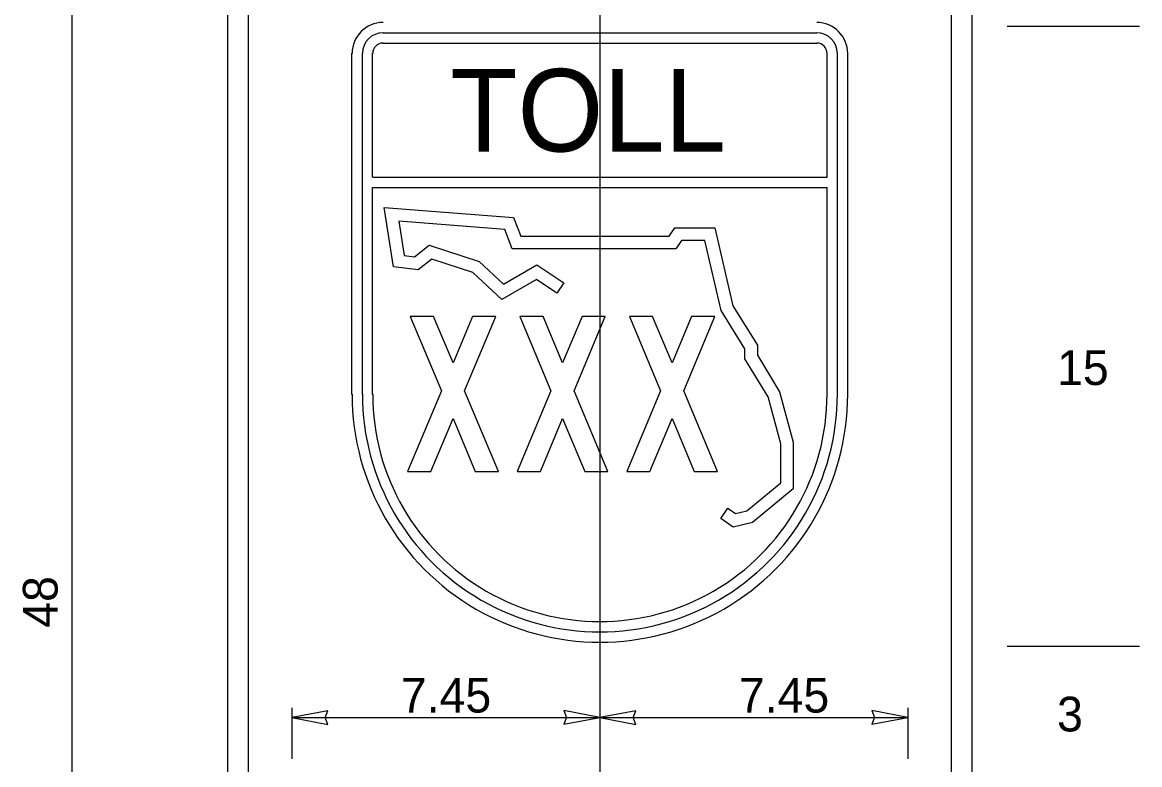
# Model space of a CAD drawing. Extents: x 56108 to 56734, y 11696 to 12110.
# Drawn here: x 56513 to 56603.2, y 11815.3 to 11875.2 of the extents above; entities that cross this region are included whole.
import ezdxf

# ---------------------------------------------------------------- set-up
doc = ezdxf.new("R2010")
doc.units = 0
for name, color, linetype in [('CL_dp', 7, 'Continuous'), ('GSDims', 7, 'Continuous'), ('SignDetail', 7, 'Continuous'), ('SignPanel', 7, 'Continuous')]:
    doc.layers.add(name, color=color, linetype=linetype)

msp = doc.modelspace()

# ---------------------------------------------------------------- linework, layer by layer
at = {"layer": 'CL_dp'}
msp.add_line((56559.633, 11917.974), (56559.633, 11745.618), dxfattribs=at)
at = {"layer": 'GSDims'}
for p, q in [((56517.038, 11913.158), (56517.038, 11753.158)), ((56603.176, 11874.825), (56592.496, 11874.825)), ((56547.759, 11858.728), (56547.759, 11858.728)), ((56603.176, 11824.825), (56592.496, 11824.825)), ((56534.799, 11819.883), (56534.799, 11815.752)), ((56537.699, 11819.631), (56534.799, 11819.091)), ((56537.479, 11819.091), (56537.699, 11819.631)), ((56559.633, 11819.091), (56556.733, 11819.651)), ((56556.733, 11819.651), (56556.953, 11819.091)), ((56562.533, 11819.631), (56559.633, 11819.091)), ((56562.313, 11819.091), (56562.533, 11819.631)), ((56584.466, 11819.091), (56581.566, 11819.651)), ((56581.566, 11819.651), (56581.786, 11819.091)), ((56584.466, 11819.883), (56584.466, 11815.752)), ((56534.799, 11819.091), (56559.633, 11819.091)), ((56534.799, 11819.091), (56537.699, 11818.531)), ((56537.699, 11818.531), (56537.479, 11819.091)), ((56556.953, 11819.091), (56556.733, 11818.551)), ((56556.733, 11818.551), (56559.633, 11819.091)), ((56559.633, 11819.091), (56584.466, 11819.091)), ((56559.633, 11819.091), (56562.533, 11818.531)), ((56562.533, 11818.531), (56562.313, 11819.091)), ((56581.786, 11819.091), (56581.566, 11818.551)), ((56581.566, 11818.551), (56584.466, 11819.091))]:
    msp.add_line(p, q, dxfattribs=at)
at = {"layer": 'SignDetail'}
for p, q in [((56542.135, 11874.323), (56577.137, 11874.323)), ((56539.636, 11845.149), (56539.636, 11872.663)), ((56540.475, 11845.149), (56540.475, 11872.663)), ((56541.295, 11862.665), (56541.295, 11872.663)), ((56542.135, 11873.483), (56577.137, 11873.483)), ((56577.957, 11862.665), (56577.957, 11872.663)), ((56578.796, 11845.149), (56578.796, 11872.663)), ((56579.636, 11845.149), (56579.636, 11872.663)), ((56541.295, 11862.665), (56577.957, 11862.665)), ((56541.295, 11845.149), (56541.295, 11861.825)), ((56541.295, 11861.825), (56577.957, 11861.825)), ((56577.957, 11845.149), (56577.957, 11861.825))]:
    msp.add_line(p, q, dxfattribs=at)
for centre, major_axis, start_param, end_param in [((56542.145, 11872.653), (0, 2.5), 0, 1.570796), ((56577.127, 11872.653), (0, 2.5), 4.712389, 6.283185), ((56542.145, 11872.653), (0, 1.666), 0, 1.570796), ((56577.127, 11872.653), (0, 1.666), 4.712389, 6.283185), ((56542.145, 11872.653), (0, 0.833), 0, 1.570796), ((56577.127, 11872.653), (0, 0.833), 4.712389, 6.283185), ((56559.636, 11845.159), (0, -19.996), 4.712389, 7.853982), ((56559.636, 11845.159), (0, -19.163), 4.712389, 7.853982), ((56559.636, 11845.159), (0, -18.33), 4.712389, 7.853982)]:
    msp.add_ellipse(centre, major_axis=major_axis, ratio=0.9997, start_param=start_param, end_param=end_param, dxfattribs=at)
at = {"layer": 'SignPanel'}
for p, q in [((56542.981, 11855.442), (56542.238, 11860.215)), ((56542.238, 11860.215), (56552.673, 11859.41)), ((56551.964, 11858.456), (56543.428, 11859.114)), ((56543.428, 11859.114), (56543.858, 11856.348)), ((56552.673, 11859.41), (56553.256, 11857.91)), ((56552.568, 11856.903), (56551.964, 11858.456)), ((56565.225, 11857.91), (56565.676, 11858.576)), ((56565.676, 11858.576), (56568.896, 11858.576)), ((56568.896, 11858.576), (56570.354, 11852.303)), ((56553.256, 11857.91), (56565.225, 11857.91)), ((56566.21, 11857.57), (56565.759, 11856.903)), ((56568.097, 11857.57), (56566.21, 11857.57)), ((56569.412, 11851.913), (56568.097, 11857.57)), ((56544.686, 11856.246), (56545.871, 11857.179)), ((56545.871, 11857.179), (56549.897, 11855.869)), ((56565.759, 11856.903), (56552.568, 11856.903)), ((56543.858, 11856.348), (56544.686, 11856.246)), ((56546.071, 11856.055), (56544.978, 11855.195)), ((56549.376, 11854.98), (56546.071, 11856.055)), ((56549.897, 11855.869), (56551.873, 11854.038)), ((56551.873, 11854.038), (56554.552, 11855.612)), ((56554.552, 11855.612), (56556.732, 11854.138)), ((56544.978, 11855.195), (56542.981, 11855.442)), ((56551.737, 11852.792), (56549.376, 11854.98)), ((56554.514, 11854.423), (56551.737, 11852.792)), ((56556.168, 11853.305), (56554.514, 11854.423)), ((56556.732, 11854.138), (56556.168, 11853.305)), ((56571.332, 11848.827), (56569.412, 11851.913)), ((56570.354, 11852.303), (56572.339, 11849.114)), ((56571.332, 11848.028), (56571.332, 11848.827)), ((56572.339, 11849.114), (56572.339, 11848.309)), ((56572.339, 11848.309), (56574.134, 11845.353)), ((56573.201, 11844.951), (56571.332, 11848.028)), ((56574.233, 11841.173), (56573.201, 11844.951)), ((56574.134, 11845.353), (56575.239, 11841.309)), ((56574.233, 11838.006), (56574.233, 11841.173)), ((56575.239, 11841.309), (56575.239, 11837.529)), ((56571.485, 11835.753), (56574.233, 11838.006)), ((56575.239, 11837.529), (56571.944, 11834.828)), ((56569.386, 11835.142), (56569.96, 11835.968)), ((56569.96, 11835.968), (56570.582, 11835.537)), ((56570.582, 11835.537), (56571.485, 11835.753)), ((56570.378, 11834.453), (56569.386, 11835.142)), ((56571.944, 11834.828), (56570.378, 11834.453))]:
    msp.add_line(p, q, dxfattribs=at)
for points in [[(56529.633, 11758.158), (56529.633, 11908.158)], [(56531.299, 11758.158), (56531.299, 11908.158)], [(56587.966, 11908.158), (56587.966, 11758.158)], [(56589.633, 11908.158), (56589.633, 11758.158)]]:
    msp.add_lwpolyline(points, dxfattribs=at)
for points in [[(56545.997, 11838.933), (56547.787, 11843.209), (56549.577, 11838.933), (56551.45, 11838.933), (56548.723, 11845.446), (56551.229, 11851.433), (56549.356, 11851.433), (56547.787, 11847.683), (56546.217, 11851.433), (56544.344, 11851.433), (56546.85, 11845.446), (56544.124, 11838.933)], [(56554.834, 11838.933), (56556.624, 11843.209), (56558.414, 11838.933), (56560.287, 11838.933), (56557.56, 11845.446), (56560.066, 11851.433), (56558.193, 11851.433), (56556.624, 11847.683), (56555.054, 11851.433), (56553.181, 11851.433), (56555.687, 11845.446), (56552.961, 11838.933)], [(56563.671, 11838.933), (56565.461, 11843.209), (56567.251, 11838.933), (56569.124, 11838.933), (56566.397, 11845.446), (56568.903, 11851.433), (56567.03, 11851.433), (56565.461, 11847.683), (56563.891, 11851.433), (56562.018, 11851.433), (56564.524, 11845.446), (56561.798, 11838.933)]]:
    msp.add_lwpolyline(points, close=True, dxfattribs=at)

# ---------------------------------------------------------------- texts
at = {"layer": 'GSDims'}
for s, p in [('15', (56596.514, 11845.907)), ('7.45', (56543.578, 11819.49)), ('7.45', (56570.849, 11819.49)), ('3', (56596.514, 11817.968))]:
    msp.add_text(s, height=2.8, dxfattribs=at).set_placement(p)
msp.add_text('48', height=2.8, rotation=90, dxfattribs=at).set_placement((56515.889, 11826.329))
at = {"layer": 'SignDetail'}
msp.add_text('TOLL', height=6.6587, dxfattribs=at).set_placement((56547.552, 11864.741))

doc.saveas('drawing.dxf')
